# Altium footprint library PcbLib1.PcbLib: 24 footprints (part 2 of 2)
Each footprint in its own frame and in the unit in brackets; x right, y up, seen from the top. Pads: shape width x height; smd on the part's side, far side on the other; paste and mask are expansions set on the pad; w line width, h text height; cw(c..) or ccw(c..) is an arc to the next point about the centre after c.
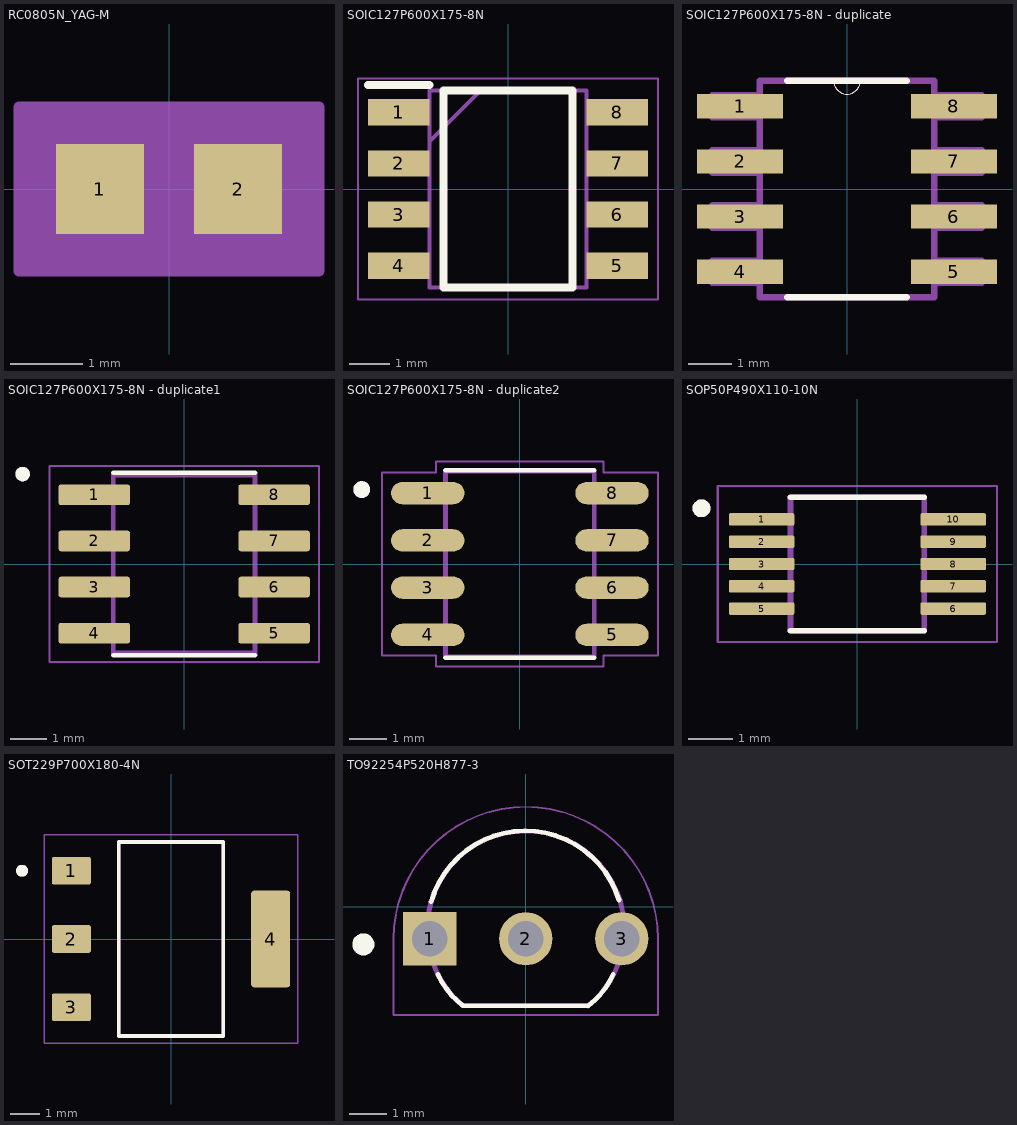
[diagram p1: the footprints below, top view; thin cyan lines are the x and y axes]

## RC0805N_YAG-M [mil]
pads (2):
  rect 48x49 smd paste+0 mask+0: 1(-37.5,0) 2(37.5,0)
Mechanical 13:
  lines w1: -39.5,-23.5 -39.5,23.5 ; -39.5,-23.5 -13.5,-23.5 -13.5,23.5 -39.5,23.5 ; -39.5,-23.5 39.5,-23.5 ; -39.5,-23.5 -39.5,23.5 ; -39.5,23.5 39.5,23.5 ; 39.5,-23.5 13.5,-23.5 13.5,23.5 39.5,23.5 ; 39.5,-23.5 39.5,23.5 ; 39.5,-23.5 39.5,23.5
Mechanical 15:
  region: 81.5,-44.5 -81.5,-44.5 -81.5,44.5 81.5,44.5
  lines w6: -81.5,-44.5 -81.5,44.5 81.5,44.5 81.5,-44.5 -81.5,-44.5
3D body "RC0805N_YAG.step": height 27.99, standoff 0, extent -39.49,-23.5 39.49,23.5

## SOIC127P600X175-8N [mm]
pads (8):
  rect 1.525x0.65 smd: 1(-2.712,1.905) 2(-2.712,0.635) 3(-2.712,-0.635) 4(-2.712,-1.905) 5(2.712,-1.905) 6(2.712,-0.635) 7(2.712,0.635) 8(2.712,1.905)
Top Overlay:
  lines w0.2: -3.475,2.58 -1.95,2.58 ; -1.6,-2.45 1.6,-2.45 1.6,2.45 -1.6,2.45 -1.6,-2.45
Mechanical 13:
  lines w0.1: -1.95,1.18 -0.68,2.45 ; -1.95,-2.45 1.95,-2.45 1.95,2.45 -1.95,2.45 -1.95,-2.45
Mechanical 15:
  lines w0.05: -3.725,-2.75 3.725,-2.75 3.725,2.75 -3.725,2.75 -3.725,-2.75
3D body "NE555DR.stp": height 1.75, standoff 0, extent -3,-2.45 3,2.45

## SOIC127P600X175-8N - duplicate [mil]
pads (8):
  rect 78x22 smd: 1(-97,75) 2(-97,25) 3(-97,-25) 4(-97,-75) 5(97,-75) 6(97,-25) 7(97,25) 8(97,75)
Top Overlay:
  lines w0: -12,98 ccw(c0,98) 12,98
  lines w6: -54,-98 54,-98 ; -54,98 -12,98 12,98 54,98
Mechanical 13:
  lines w0: -12,98 ccw(c0,98) 12,98
  lines w6: -122,-85 -79,-85 -79,-65 -122,-65 -122,-85 ; -122,-35 -79,-35 -79,-15 -122,-15 -122,-35 ; -122,15 -79,15 -79,35 -122,35 -122,15 ; -122,65 -79,65 -79,85 -122,85 -122,65 ; -79,-98 -79,98 -12,98 12,98 79,98 79,-98 -79,-98 ; 79,-85 122,-85 122,-65 79,-65 79,-85 ; 79,-35 122,-35 122,-15 79,-15 79,-35 ; 79,15 122,15 122,35 79,35 79,15 ; 79,65 122,65 122,85 79,85 79,65
3D body "step_temp.STEP": height 68.9, standoff 0, extent -118.11,-96.46 118.11,96.46

## SOIC127P600X175-8N - duplicate1 [mm]
pads (8):
  rrect25% 1.97x0.57 smd paste+0 mask+0.102: 1(-2.475,1.905) 2(-2.475,0.635) 3(-2.475,-0.635) 4(-2.475,-1.905) 5(2.475,-1.905) 6(2.475,-0.635) 7(2.475,0.635) 8(2.475,1.905)
Top Overlay:
  circle w0.2: c-4.445,2.475 r0.1
  lines w0.127: -1.95,-2.51 1.95,-2.51 ; -1.95,2.51 1.95,2.51
Mechanical 13:
  circle w0.2: c-4.445,2.475 r0.1
  lines w0.127: -1.95,-2.45 1.95,-2.45 1.95,2.45 -1.95,2.45 -1.95,-2.45
Mechanical 15:
  lines w0.05: -3.71,-2.7 3.71,-2.7 3.71,2.7 -3.71,2.7 -3.71,-2.7
3D body "step_temp.STEP": height 1.75, standoff 0, extent -2.995,-2.452 2.995,2.452

## SOIC127P600X175-8N - duplicate2 [mm]
pads (8):
  oval 1.97x0.6 smd: 1(-2.475,1.905) 2(-2.475,0.635) 3(-2.475,-0.635) 4(-2.475,-1.905) 5(2.475,-1.905) 6(2.475,-0.635) 7(2.475,0.635) 8(2.475,1.905)
Top Overlay:
  circle w0.25: c-4.25,2 r0.1
  lines w0.127: -2,-2.519 2,-2.519 ; -2,2.519 2,2.519
Mechanical 13:
  circle w0.25: c-4.25,2 r0.1
  lines w0.127: -2,-2.5 2,-2.5 2,2.5 -2,2.5 -2,-2.5
Mechanical 15:
  lines w0.05: -3.71,-2.46 -2.25,-2.46 -2.25,-2.75 2.25,-2.75 2.25,-2.46 3.71,-2.46 3.71,2.46 2.25,2.46 2.25,2.75 -2.25,2.75 -2.25,2.46 -3.71,2.46 -3.71,-2.46
3D body "step_temp.STEP": height 1.75, standoff 0, extent -3,-2.45 3,2.45

## SOP50P490X110-10N [mm]
pads (10):
  rrect25% 1.47x0.28 smd: 1(-2.15,1) 2(-2.15,0.5) 3(-2.15,0) 4(-2.15,-0.5) 5(-2.15,-1) 6(2.15,-1) 7(2.15,-0.5) 8(2.15,0) 9(2.15,0.5) 10(2.15,1)
Top Overlay:
  circle w0.2: c-3.5,1.25 r0.1
  lines w0.127: -1.5,-1.5 1.5,-1.5 ; -1.5,1.5 1.5,1.5
Mechanical 13:
  circle w0.2: c-3.5,1.25 r0.1
  lines w0.127: -1.5,-1.5 1.5,-1.5 1.5,1.5 -1.5,1.5 -1.5,-1.5
Mechanical 15:
  lines w0.05: -3.135,-1.75 3.135,-1.75 3.135,1.75 -3.135,1.75 -3.135,-1.75
3D body "step_temp.STEP": height 1.1, standoff 0, extent -2.45,-1.5 2.45,1.5

## SOT229P700X180-4N [mm]
height 1.8
pads (4):
  rrect15% 1.31x0.93 smd: 1(-3.345,2.29) 2(-3.345,0) 3(-3.345,-2.29)
  rrect15% 1.31x3.24 smd: 4(3.345,0)
Top Overlay:
  circle w0.2: c-5,2.29 r0.1
  lines w0.127: -1.753,-3.253 1.753,-3.253 1.753,3.253 -1.753,3.253 -1.753,-3.253
Mechanical 13:
  circle w0.2: c-5,2.29 r0.1
  lines w0.127: -1.753,-3.253 1.753,-3.253 1.753,3.253 -1.753,3.253 -1.753,-3.253
Mechanical 15:
  lines w0.05: -4.25,-3.502 -4.25,3.502 4.25,3.502 4.25,-3.502 -4.25,-3.502
3D body "step_temp.STEP": height 1.8, standoff 0, extent -3.251,-3.499 3.251,3.499

## TO92254P520H877-3 [mm]
pads (3):
  rect 1.41x1.41 / inner round 1.41 / far side rect 1.41x1.41 hole 0.94: 1(-2.54,-0.853)
  round 1.41 hole 0.94: 2(0,-0.853) 3(2.54,-0.853)
Top Overlay:
  circle w0.3: c-4.3,-1 r0.141
  lines w0.127: -2.506,0.128 cw(c-0.013,-0.587) 2.468,0.172 ; -2.326,-1.791 ccw(c-0.4,-0.934) -1.669,-2.617 ; -1.661,-2.623 1.661,-2.623 ; 1.659,-2.618 ccw(c0.39,-0.935) 2.316,-1.792
Mechanical 13:
  lines w0.127: -1.679,-2.608 cw(c0,-0.608) 1.643,-2.637 ; -1.661,-2.623 1.661,-2.623
Mechanical 15:
  lines w0.05: -3.5,-2.873 -3.5,-0.857 cw(c0,-0.857) 3.5,-0.857 3.5,-2.873 -3.5,-2.873
3D body "step_temp.STEP": height 8.77, standoff -13, extent -2.83,-1.43 2.83,2.19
